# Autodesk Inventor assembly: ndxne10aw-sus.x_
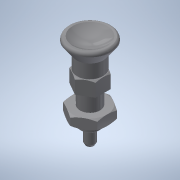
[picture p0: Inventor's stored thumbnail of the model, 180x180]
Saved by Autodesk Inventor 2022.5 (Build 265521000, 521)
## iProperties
Part Number: ndxne10aw-sus.x_
Material: 一般
Document SubType Name: Assembly
Designer: ImaoCorp
Sending System: SOLIDWORKS 2017-2017317
MC: AMD64
MC_MODEL: Intel64 Family 6 Model 60 Stepping 3, GenuineIntel
OS: Windows_NT
FRU: Parasolid Version 29.0, build 201,  4-17-2017
FORMAT: text
GUISE: transmit
KEY: ndxne10aw-sus
FILE: ndxne10aw-sus.x_t
DATE: Wed Sep 04 15:27:05 2019
Author: ImaoCorp
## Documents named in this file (3)
- X:\14_SW2022-Inv2022\00_全2023-1023新製品(TCC)まで\n\ndxne10aw-sus\NDXNE10AW-SUS.iam
- X:\14_SW2022-Inv2022\00_全2023-1023新製品(TCC)まで\n\ndxne10aw-sus\ndxne10aw-sus_01.ipt
- X:\14_SW2022-Inv2022\00_全2023-1023新製品(TCC)まで\n\ndxne10aw-sus\ndxne10aw-sus_02.ipt
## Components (2 placed, 2 different names)
1. ndxne10aw-sus_01
2. ndxne10aw-sus_02
